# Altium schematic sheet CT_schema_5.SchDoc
size 245 x 200 mm
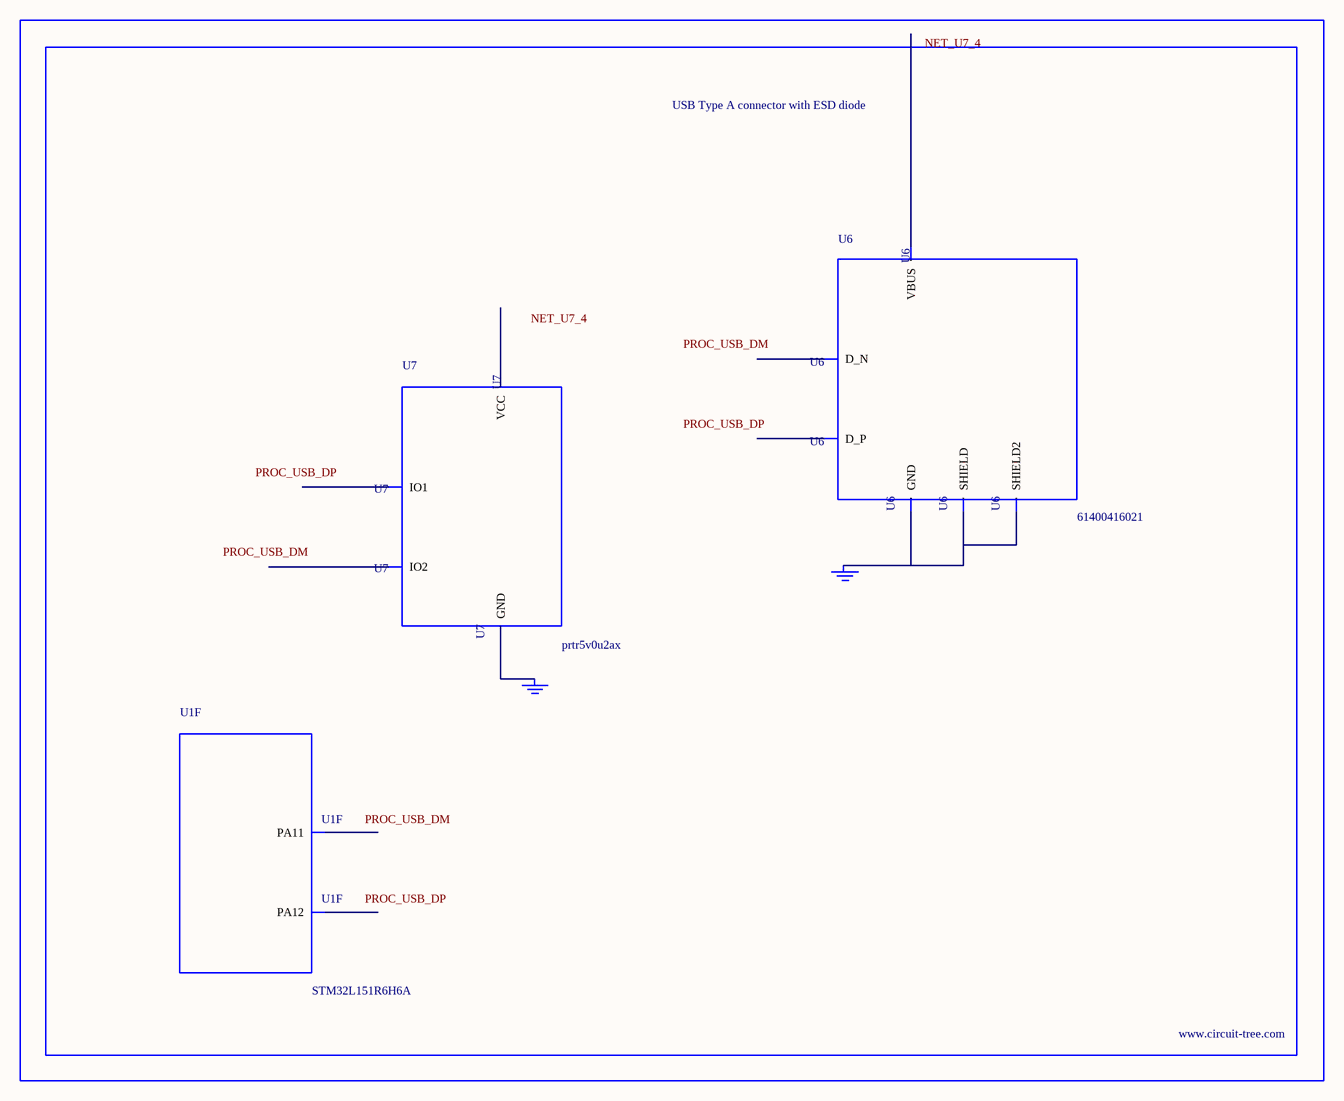
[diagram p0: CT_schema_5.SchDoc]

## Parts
BORDER4  (no value)
GND_INSTANCE_4_0  (no value)
GND_INSTANCE_4_1  (no value)
U1  STM32L151R6H6A  [TFBGA64]  (part F of 7)
U6  61400416021  [USB-A-H]
U7  prtr5v0u2ax  [SOT143B]

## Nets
NetGND_INSTANCE_4_0_0: GND_INSTANCE_4_0.0(GND) U6.4(GND) U6.5(SHIELD) U6.6(SHIELD2)
NetGND_INSTANCE_4_1_0: GND_INSTANCE_4_1.0(GND) U7.1(GND)

Not connected (* = marked no-connect by the designer): U1 B8(PA12) C8(PA11); U6 1(VBUS) 2(D_N) 3(D_P); U7 2(IO1) 3(IO2) 4(VCC)

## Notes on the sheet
- Labels drawn without touching a wire or pin: NET_U7_4, PROC_USB_DM, PROC_USB_DP

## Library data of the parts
BORDER4 = BORDER_PAGE4
GND_INSTANCE_4_0 GND_INSTANCE_4_1 = GND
